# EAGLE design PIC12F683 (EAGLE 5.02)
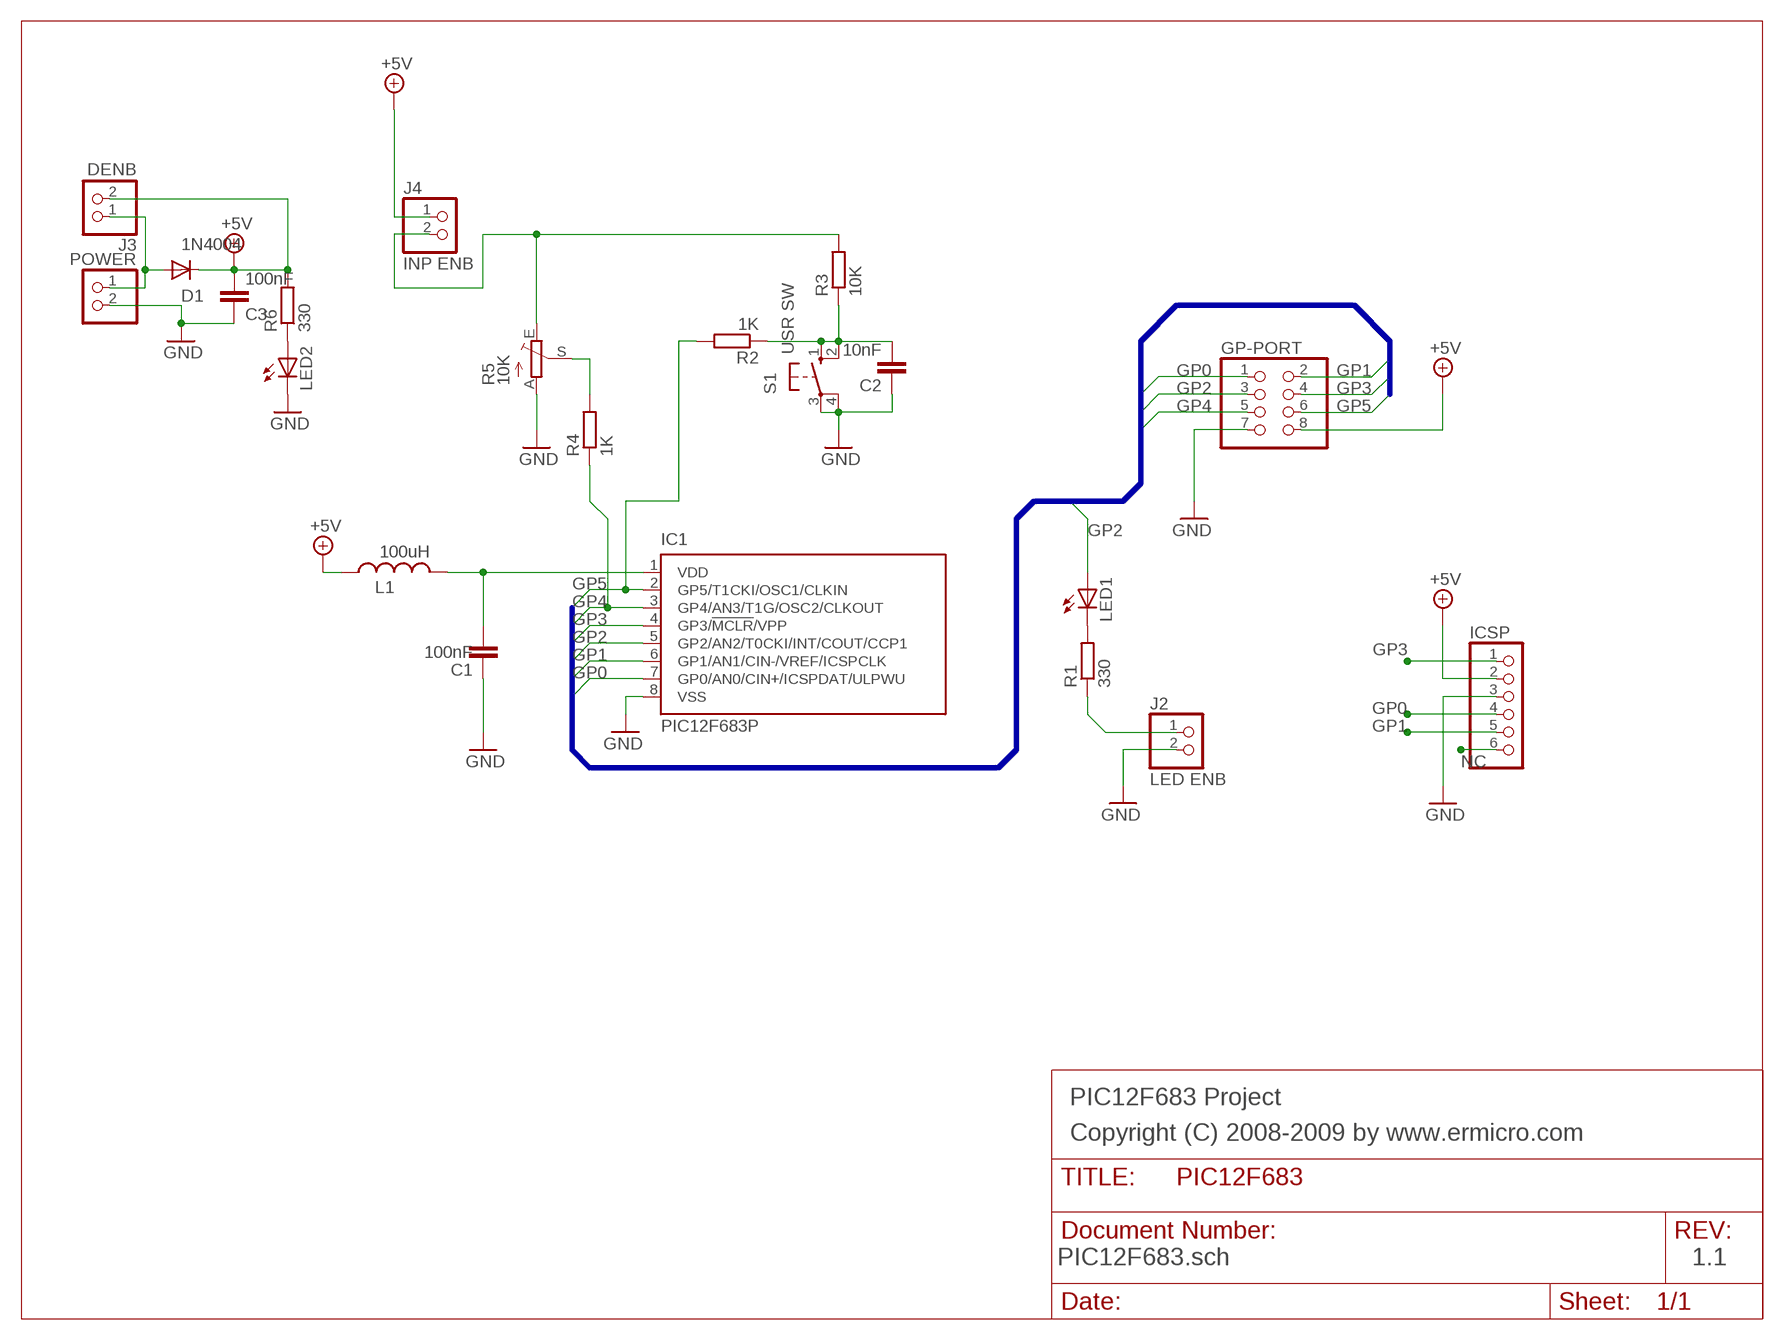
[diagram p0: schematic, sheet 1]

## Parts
C1  100nF  C-EU050-024X044  [C050-024X044]
C2  10nF  C-EU050-024X044  [C050-024X044]
C3  100nF  C-EU050-024X044  [C050-024X044]
D1  1N4004  [DO41-10]
GP-PORT  PINHD-2X4  [2X04]
IC1  PIC12F683P  [DIL8]
ICSP  PINHD-1X6  [1X06]
J2  LED ENB  PINHD-1X2  [1X02]
J3  DENB  PINHD-1X2  [1X02]
J4  INP ENB  PINHD-1X2  [1X02]
L1  100uH  L-US0207/10  [0207/10]
LED1  LED3MM  [LED3MM]
LED2  LED3MM  [LED3MM]
POWER  PINHD-1X2  [1X02]
R1  330  R-EU_0207/10  [0207/10]
R2  1K  R-EU_0207/10  [0207/10]
R3  10K  R-EU_0207/10  [0207/10]
R4  1K  R-EU_0207/10  [0207/10]
R5  10K  TRIM_EU-B25P  [B25P]
R6  330  R-EU_0207/10  [0207/10]
S1  USR SW  10-XX  [B3F-10XX]

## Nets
+5V: C3.2 D1.C GP-PORT.8 ICSP.2 J3.2 J4.1 L1.1 R6.2
GND: C1.1 C2.1 C3.1 GP-PORT.7 IC1.8(VSS) ICSP.3 J2.2 LED2.K(C) POWER.2 R5.A S1.3(P) S1.4(P1)
GP0: GP-PORT.1 IC1.7(GP0/AN0/CIN+/ICSPDAT/ULPWU) ICSP.4
GP1: GP-PORT.2 IC1.6(GP1/AN1/CIN-/VREF/ICSPCLK) ICSP.5
GP2: GP-PORT.3 IC1.5(GP2/AN2/T0CKI/INT/COUT/CCP1) LED1.A
GP3: GP-PORT.4 IC1.4(GP3/!MCLR!/VPP) ICSP.1
GP4: GP-PORT.5 IC1.3(GP4/AN3/T1G/OSC2/CLKOUT) R4.1
GP5: GP-PORT.6 IC1.2(GP5/T1CKI/OSC1/CLKIN) R2.2
N$1: LED1.K(C) R1.2
N$3: J4.2 R3.2 R5.E
N$4: J2.1 R1.1
N$6: C2.2 R2.1 R3.1 S1.1(S) S1.2(S1)
N$17: LED2.A R6.1
N$19: D1.A J3.1 POWER.1
N$20: R4.2 R5.S
NC: ICSP.6
VDD: C1.2 IC1.1(VDD) L1.2

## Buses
B$1

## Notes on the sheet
- PIC12F683 Project
- Copyright (C) 2008-2009 by www.ermicro.com
- PIC12F683.sch
- 1.1

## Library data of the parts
C1-C3 = rcl:C-EU: CAPACITOR, European symbol
D1 = diode:1N4004: DIODE
GP-PORT = pinhead:PINHD-2X4: PIN HEADER
IC1 = microchip:PIC12F683: 8-Pin Flash-Based, 8-Bit CMOS Microcontrollers with nanoWatt Technology Source: http://ww1.microchip.com/downloads/en/DeviceDoc/41211D_.pdf
ICSP = pinhead:PINHD-1X6: PIN HEADER
J2-J4 POWER = pinhead:PINHD-1X2: PIN HEADER
L1 = rcl:L-US: INDUCTOR, American symbol
LED1 LED2 = led:LED: LED
R1-R4 R6 = rcl:R-EU_: RESISTOR, European symbol
R5 = pot:TRIM_EU-: POTENTIOMETER
S1 = switch-omron:10-XX: OMRON SWITCH

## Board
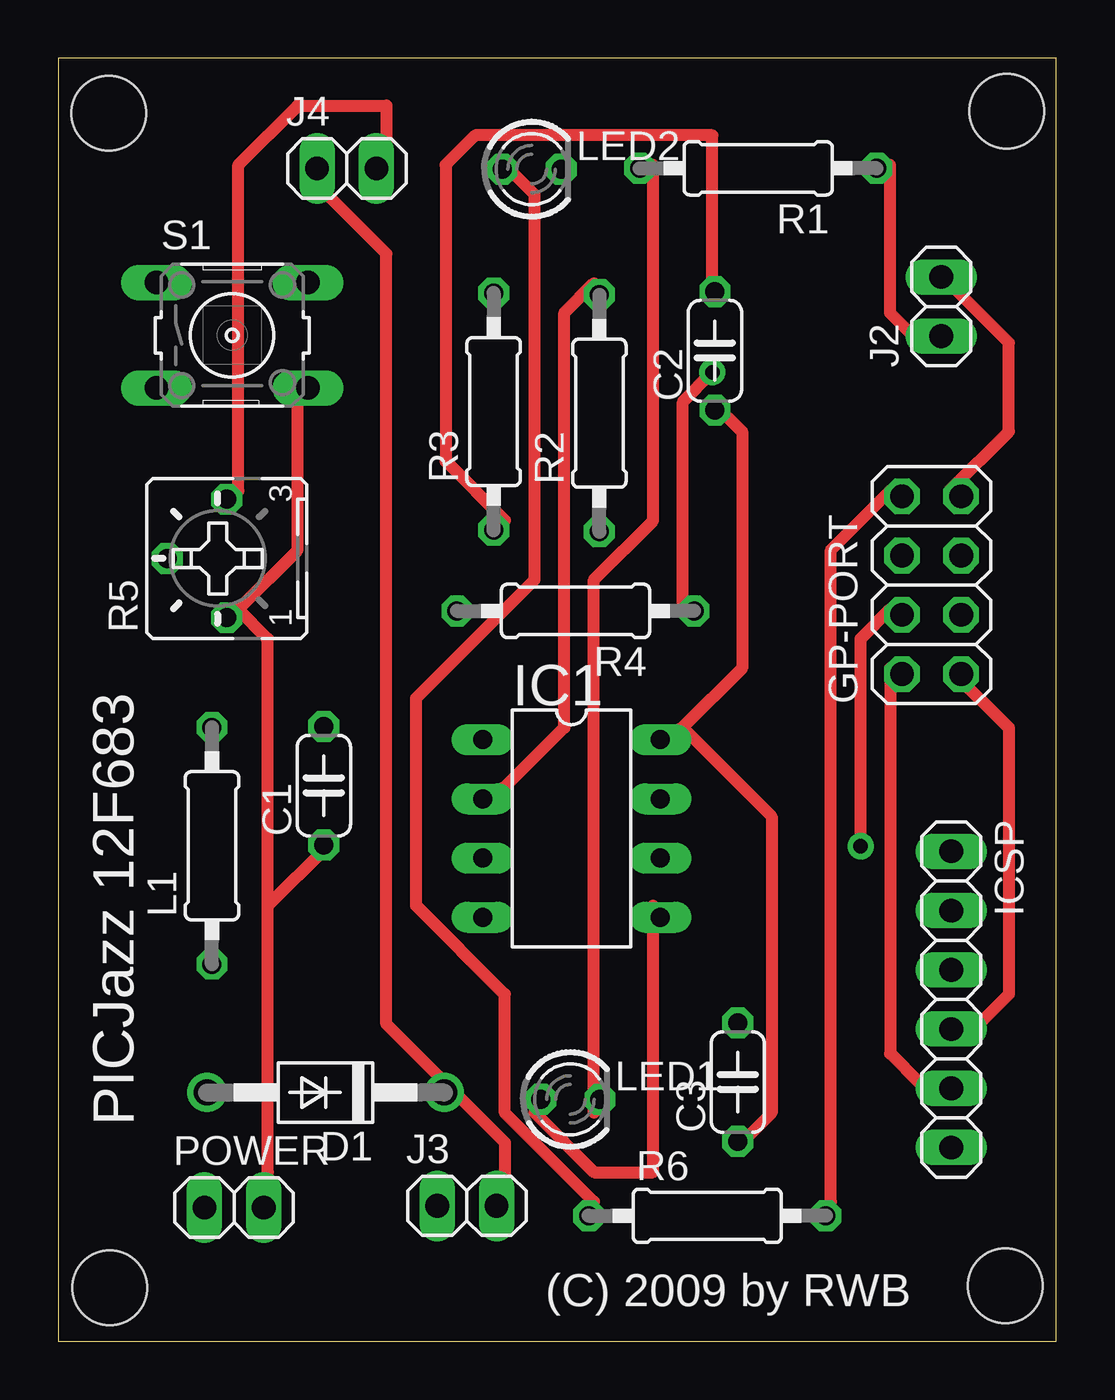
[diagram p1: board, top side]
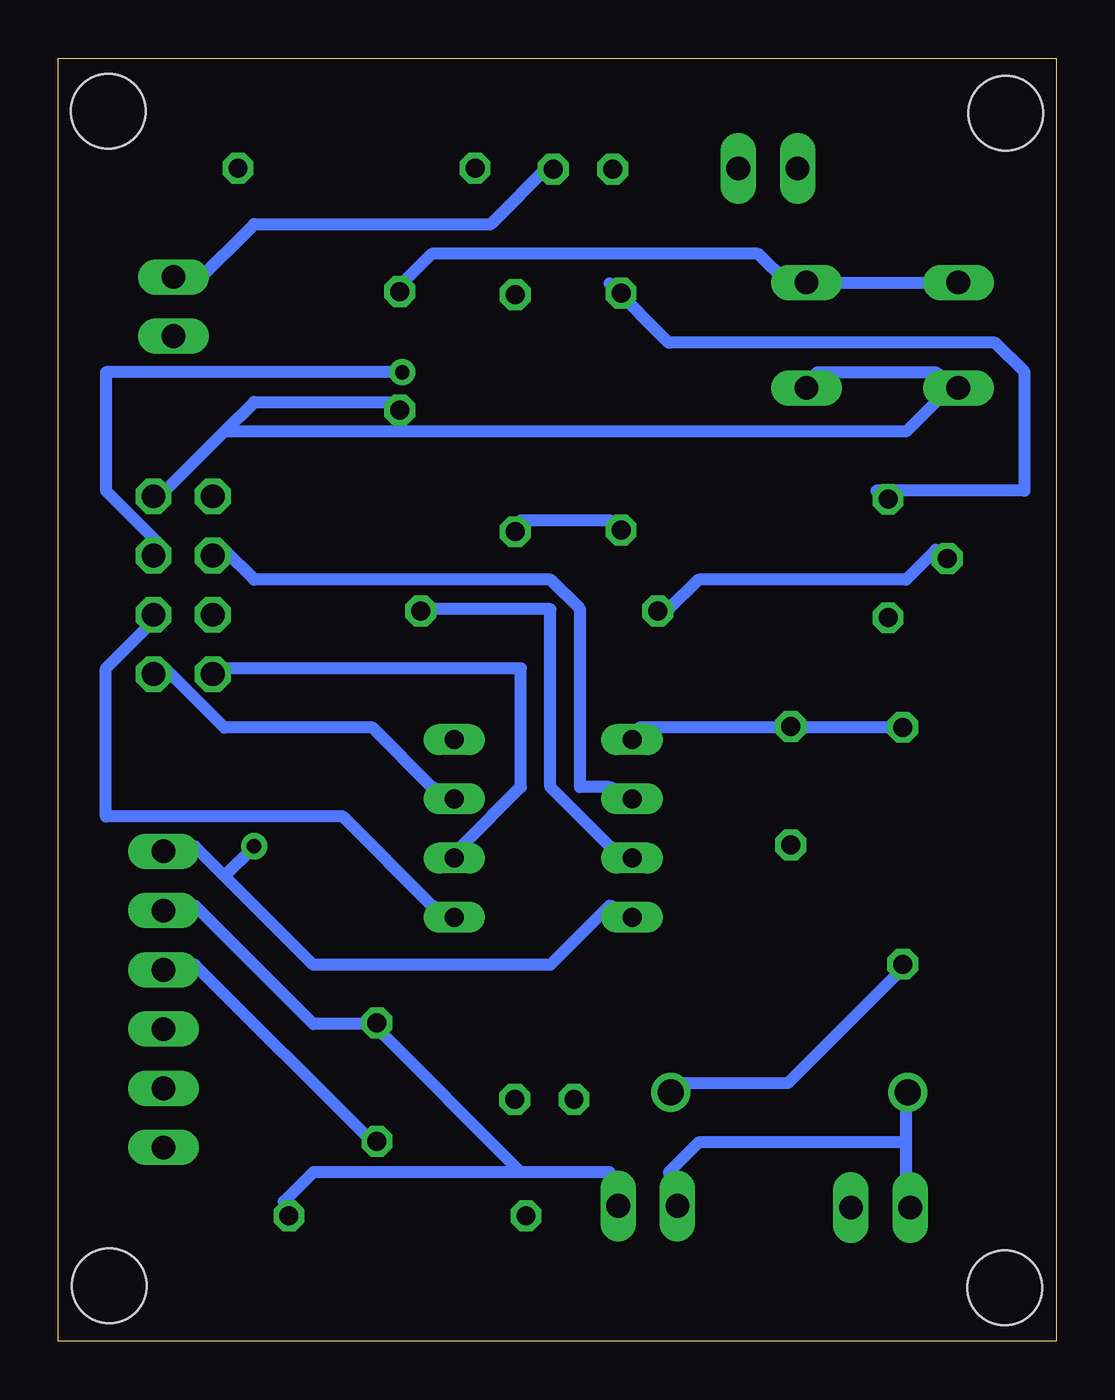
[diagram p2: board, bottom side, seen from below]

Size 42.77 x 55 mm. Coordinates in mm from the lower left corner, seen from the top.
Outline: 0,0 42.77,0 42.77,55 0,55 0,0
Copper layers (1*16): Top 0.035mm / dielectric 1.5mm / Bottom 0.035mm
Design rules "default *": minimum track width 20mil, minimum drill 24mil, track to track 10mil, track to pad 10mil, pad to pad 10mil, via to via 10mil, smd to smd 10mil, copper to edge 40mil, drill to drill 10mil, minimum pad ring 10mil, minimum via ring 10mil, stop-mask expansion 4mil, vias tented up to drill 0mil, thermal gap 10mil
Holes 3.2 mm at 2.16,52.64 40.64,52.74 40.58,2.37 2.2,2.29

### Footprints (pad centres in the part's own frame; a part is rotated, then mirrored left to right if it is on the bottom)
C050-024X044 = drill 0.813 octagon: 1 -2.54,0; 2 2.54,0
DO41-10 = drill 1.118 round: A 5.08,0; C -5.08,0
2X04 = drill 1.016 octagon: 1 -3.81,-1.27; 2 -3.81,1.27; 3 -1.27,-1.27; 4 -1.27,1.27; 5 1.27,-1.27; 6 1.27,1.27; 7 3.81,-1.27; 8 3.81,1.27
DIL8 = drill 0.813 long: 1 -3.81,-3.81; 2 -1.27,-3.81; 3 1.27,-3.81; 4 3.81,-3.81; 5 3.81,3.81; 6 1.27,3.81; 7 -1.27,3.81; 8 -3.81,3.81
1X06 = drill 1.016 long: 1 -6.35,0; 2 -3.81,0; 3 -1.27,0; 4 1.27,0; 5 3.81,0; 6 6.35,0
1X02 = drill 1.016 long: 1 -1.27,0; 2 1.27,0
0207/10 = drill 0.813 octagon: 1 -5.08,0; 2 5.08,0
LED3MM = drill 0.813 octagon: A -1.27,0; K 1.27,0
B25P = drill 0.813 octagon: A -2.54,0; E 2.54,0; S 0,2.54
B3F-10XX = drill 1.016 long: 1 -3.251,2.261; 2 3.251,2.261; 3 -3.251,-2.261; 4 3.251,-2.261

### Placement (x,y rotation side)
C1  11.38,23.82 90 top
C2  28.14,42.46 90 top
C3  29.12,11.11 90 top
D1  11.45,10.66 180 top
GP-PORT  37.42,32.41 90 top
IC1  21.99,21.98 270 top
ICSP  38.27,14.65 270 top
J2  37.84,44.36 90 top
J3  17.51,5.8 0 top
J4  12.36,50.28 0 top
L1  6.58,21.24 90 top
LED1  21.94,10.37 0 top
LED2  20.29,50.25 0 top
POWER  7.53,5.73 0 top
R1  29.99,50.28 180 top
R2  23.19,39.78 90 top
R3  18.66,39.85 90 top
R4  22.16,31.31 180 top
R5  7.21,33.56 90 top
R6  27.81,5.38 0 top
S1  7.45,43.13 0 top

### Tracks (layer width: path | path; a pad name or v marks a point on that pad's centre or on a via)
+5V
  Top 0.508: 16.6,11.06 14.06,13.6 14.06,46.62 11.52,49.16 J4.1 | GP-PORT.8 35.65,36.46 33.11,33.92 33.11,5.98 R6.2 | 16.6,11.06 19.14,8.52 19.14,7.25 J3.2 | D1.C 16.6,11.06
  Bottom 0.508: L1.1 6.44,16.14 11.52,11.06 16.6,11.06 D1.C | 22.95,7.25 19.14,7.25 J3.2 | 22.95,7.25 31.84,7.25 33.11,5.98 R6.2 | 22.95,7.25 29.3,13.6 | 29.3,13.6 31.84,13.6 36.92,18.68 ICSP.2 | 29.3,13.6 C3.2
GND
  Top 0.508: 7.71,31.38 10.25,33.92 10.25,40.27 S1.4 | 8.98,18.68 11.52,21.22 C1.1 | 8.98,18.68 8.98,7.25 POWER.2 | 7.71,31.38 8.98,30.11 8.98,18.68 | 7.71,31.38 R5.A | 26.76,26.3 29.3,28.84 29.3,39 28.03,40.27 C2.1 | 26.76,26.3 30.57,22.49 30.57,9.79 29.3,8.52 C3.1 | 26.76,26.3 IC1.8 | J2.2 38.19,45.35 40.73,42.81 40.73,39 38.19,36.46 GP-PORT.7
  Bottom 0.508: S1.4 10.25,41.54 5.17,41.54 S1.3 5.17,40.27 6.44,39 35.65,39 | LED2.K 21.68,50.43 24.22,47.89 34.38,47.89 36.92,45.35 J2.2 | C3.1 29.3,8.52 36.92,16.14 ICSP.3 | 35.65,39 34.38,40.27 28.03,40.27 C2.1 | 35.65,39 38.19,36.46 GP-PORT.7
GP0
  Top 0.508: ICSP.4 39.46,13.6 40.73,14.87 40.73,26.3 38.19,28.84 GP-PORT.1
  Bottom 0.508: IC1.7 26.76,23.76 29.3,26.3 35.65,26.3 38.19,28.84 GP-PORT.1
GP1
  Top 0.508: ICSP.5 36.92,11.06 35.65,12.33 35.65,28.84 GP-PORT.2
  Bottom 0.508: IC1.6 25.49,21.22 22.95,23.76 22.95,28.84 35.65,28.84 GP-PORT.2
GP2
  Top 0.508: LED1.A 20.41,9.79 22.95,7.25 25.49,7.25 25.49,18.68 IC1.5
  Bottom 0.508: GP-PORT.3 38.19,31.38 40.73,28.84 40.73,22.49 30.57,22.49 26.76,18.68 IC1.5
GP3  (via drill 0.61)
  Top 0.508: v34.38,21.22 34.38,30.11 35.65,31.38 GP-PORT.4
  Bottom 0.508: 35.65,19.95 36.92,21.22 ICSP.1 | 35.65,19.95 31.84,16.14 21.68,16.14 19.14,18.68 IC1.4 | 35.65,19.95 v34.38,21.22
GP4  (via drill 0.61)
  Top 0.508: v28.03,41.54 26.76,40.27 26.76,31.38 R4.1
  Bottom 0.508: IC1.3 19.14,21.22 21.68,23.76 21.68,31.38 26.76,31.38 R4.1 | v28.03,41.54 40.73,41.54 40.73,36.46 38.19,33.92 GP-PORT.5
GP5
  Top 0.508: IC1.2 19.14,23.76 21.68,26.3 21.68,44.08 22.95,45.35 R2.2
  Bottom 0.508: GP-PORT.6 35.65,33.92 34.38,32.65 21.68,32.65 20.41,31.38 20.41,23.76 19.14,23.76 IC1.2
N$1
  Top 0.508: LED1.K 22.95,9.79 22.95,32.65 25.49,35.19 25.49,50.43 R1.2
N$3
  Top 0.508: R5.E 7.71,36.46 7.71,50.43 10.25,52.97 14.06,52.97 14.06,50.43 J4.2
  Bottom 0.508: R3.2 19.14,45.35 16.6,42.81 2.63,42.81 1.36,41.54 1.36,36.46 7.71,36.46 R5.E
N$4
  Top 0.508: R1.1 35.65,50.43 35.65,44.08 36.92,42.81 J2.1
N$6
  Top 0.508: R3.1 19.14,35.19 16.6,37.73 16.6,50.43 17.87,51.7 28.03,51.7 28.03,45.35 C2.2
  Bottom 0.508: R2.1 22.95,35.19 19.14,35.19 R3.1 | C2.2 28.03,45.35 26.76,46.62 12.79,46.62 11.52,45.35 S1.2 10.25,45.35 5.17,45.35 S1.1
N$17
  Top 0.508: R6.1 22.95,5.98 19.14,9.79 19.14,14.87 15.33,18.68 15.33,27.57 20.41,32.65 20.41,49.16 19.14,50.43 LED2.A
N$19
  Bottom 0.508: 6.44,8.52 6.44,11.06 D1.A | 6.44,8.52 6.44,7.25 POWER.1 | 6.44,8.52 15.33,8.52 16.6,7.25 J3.1
N$20
  Bottom 0.508: R5.S 5.17,33.92 6.44,32.65 15.33,32.65 16.6,31.38 R4.2
VDD
  Bottom 0.508: 11.52,26.3 6.44,26.3 L1.2 | 11.52,26.3 17.87,26.3 IC1.1 | 11.52,26.3 C1.2

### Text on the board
tNames: PICJazz 12F683 | (C) 2009 by RWB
